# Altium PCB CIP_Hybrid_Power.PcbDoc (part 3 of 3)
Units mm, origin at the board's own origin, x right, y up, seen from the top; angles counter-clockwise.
Board outline 70 x 70 mm, 4 copper layers (Top Layer, GND Pour Layer, Signal Layer 1, Bottom Layer), stack 1.68 mm thick; 202 components, 120 nets, 578 pads, 363 vias.
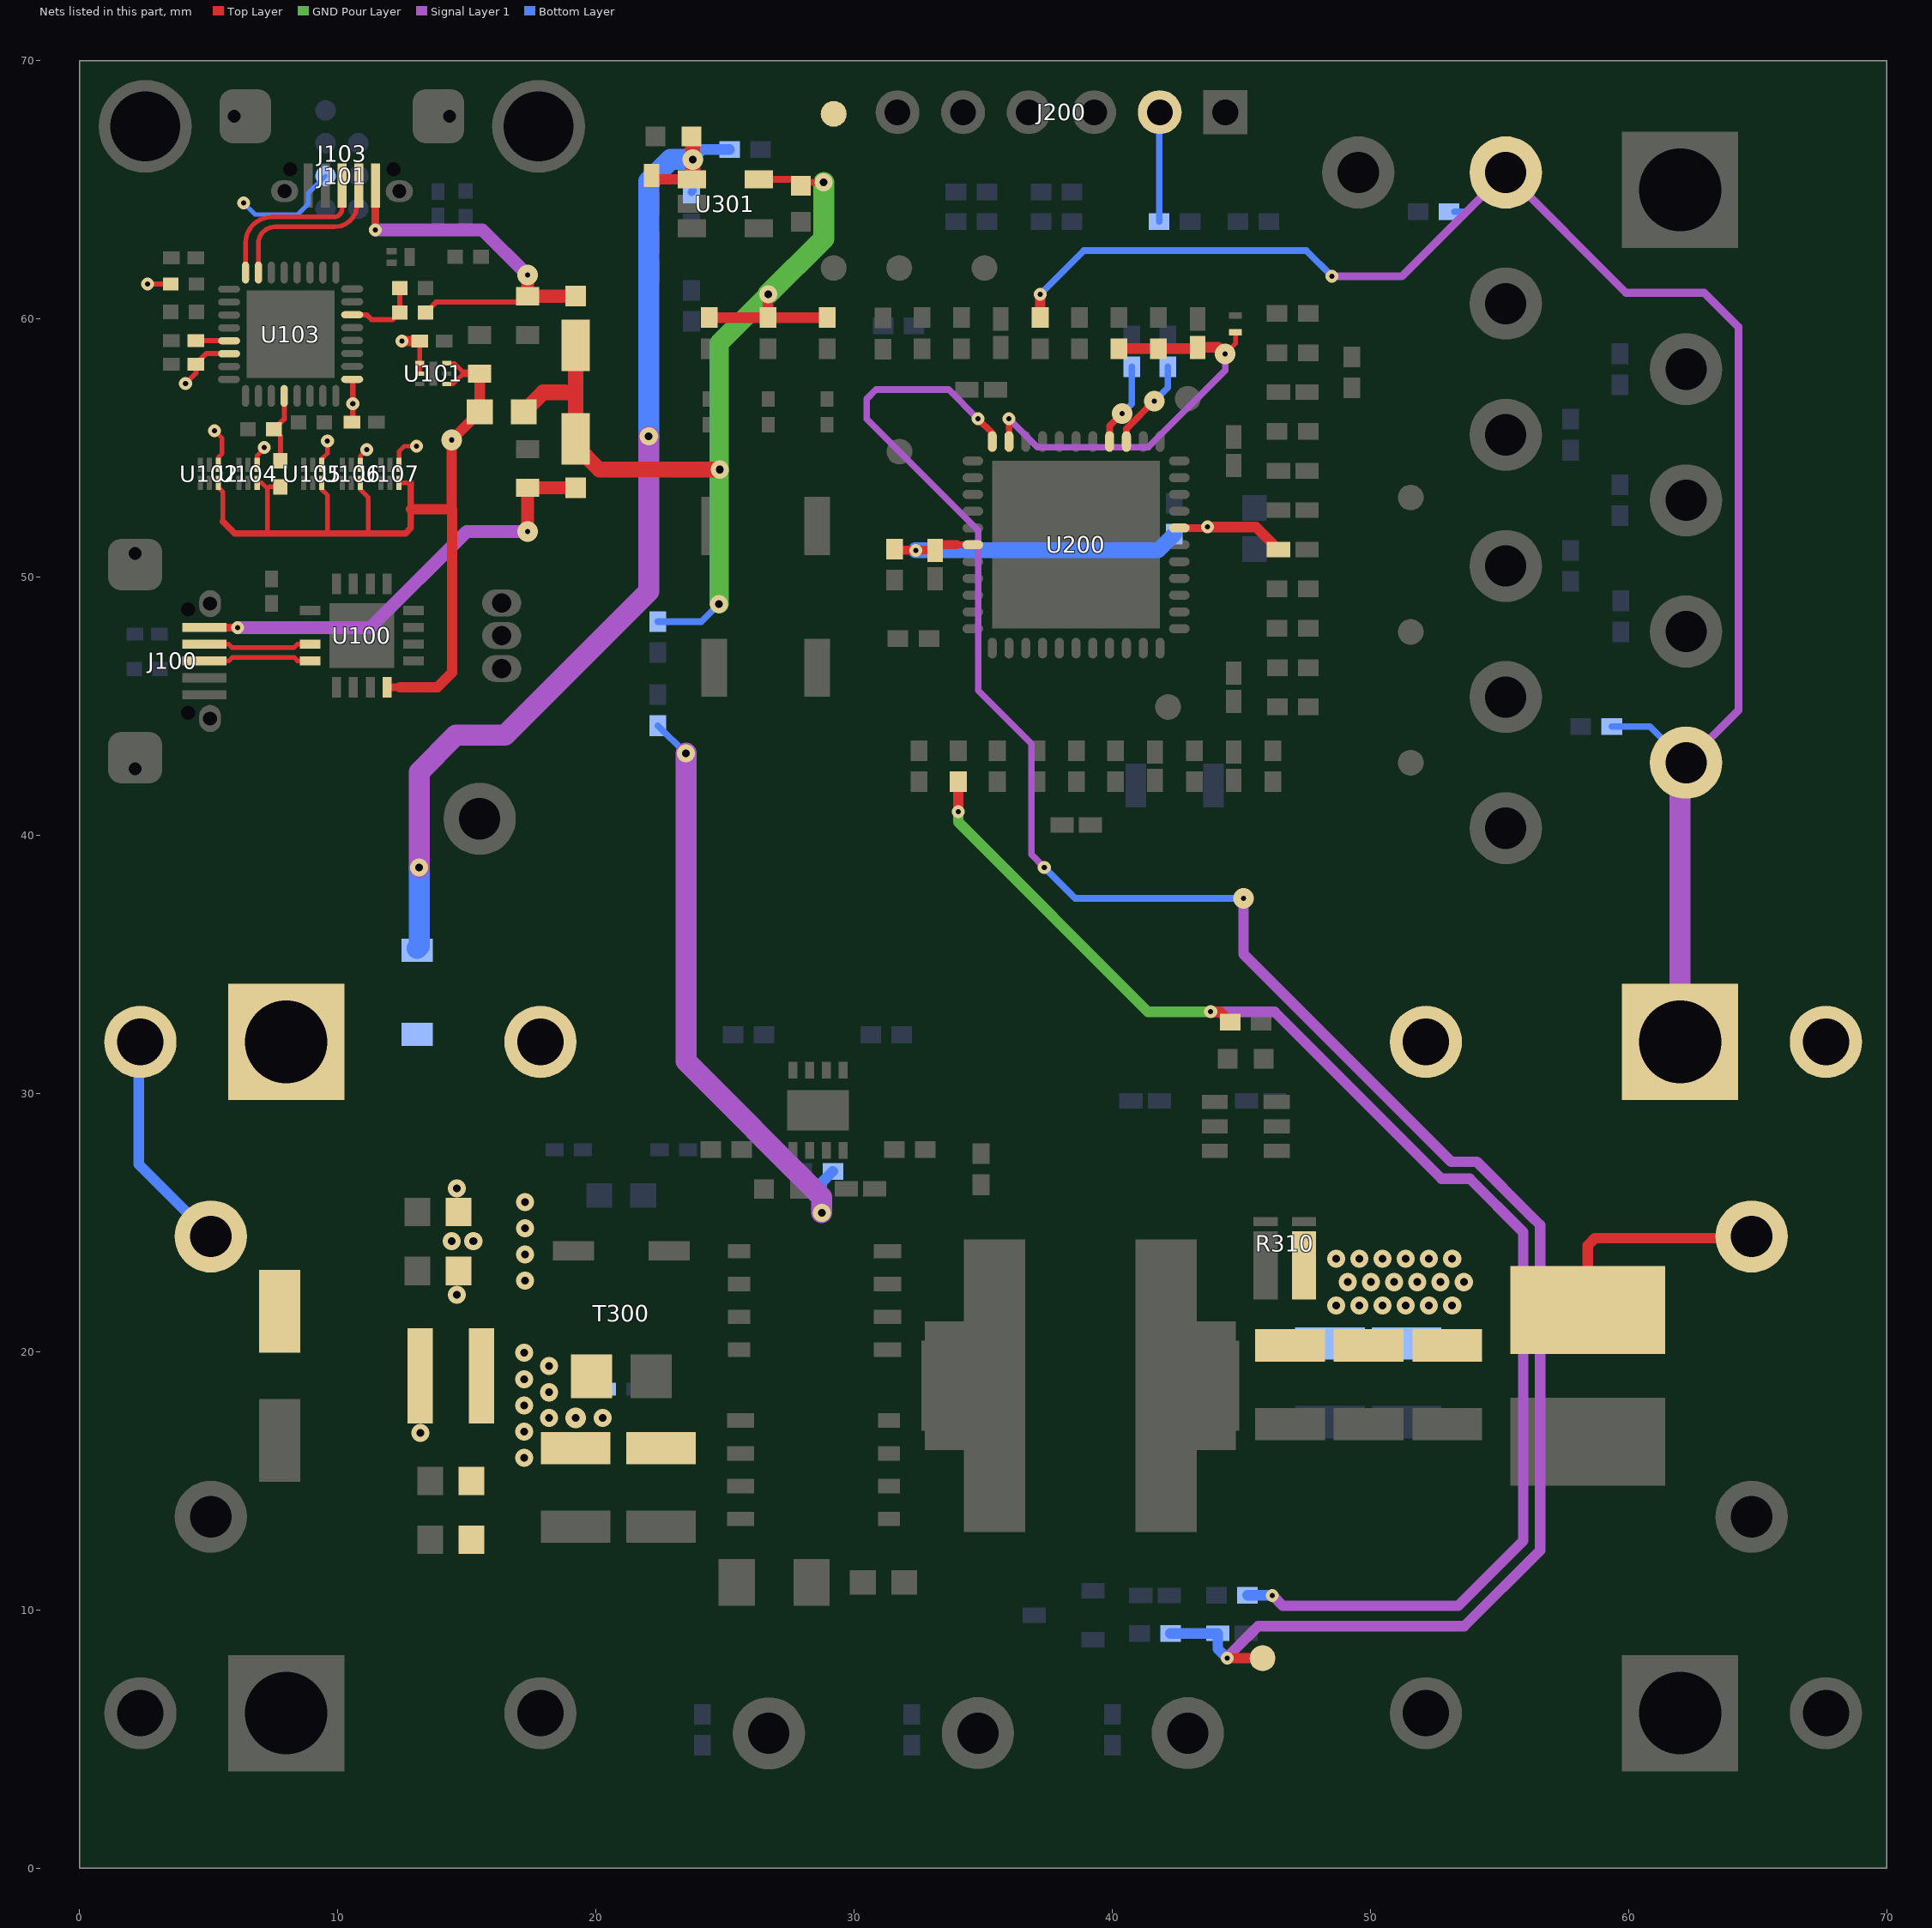
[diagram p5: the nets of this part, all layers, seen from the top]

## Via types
v1: diameter 0.7, hole 0.3, Top Layer to Bottom Layer, 181 vias
v2: diameter 0.5, hole 0.2, Top Layer to Bottom Layer, 103 vias
v3: diameter 0.5/0.5/0.5/0.8 (per signal layer), hole 0.2, Top Layer to Bottom Layer, tented top, 55 vias
v4: diameter 0.7, hole 0.3, Top Layer to Bottom Layer, tented top, 13 vias
v5: diameter 0.7/0.7/0.7/0.8 (per signal layer), hole 0.3, Top Layer to Bottom Layer, tented top, 10 vias
v6: diameter 0.5, hole 0.2, Top Layer to Bottom Layer, tented top, 1 vias

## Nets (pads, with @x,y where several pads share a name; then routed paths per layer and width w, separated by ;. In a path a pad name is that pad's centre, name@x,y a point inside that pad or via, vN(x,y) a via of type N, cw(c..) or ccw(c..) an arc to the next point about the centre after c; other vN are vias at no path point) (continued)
TEMP: C300.2 R300.2 TP203.1 U200.22 | length 84
  Top Layer w0.254: v2(34.798,56.134) 35.35,55.582 U200.22@35.35,55.253
  Top Layer w0.406: v2(44.45,8.128) TP203.1@45.824,8.128
  Signal Layer 1 w0.254: v2(34.798,56.134) 33.663,57.269 30.855,57.269 30.488,56.902 30.488,56.124 34.804,51.807 34.804,45.615 36.865,43.555 36.865,39.259 v2(37.368,38.756)
  Signal Layer 1 w0.406: v2(44.45,8.128) 44.45,8.166 45.65,9.366 53.638,9.366 56.574,12.302 56.574,24.905 56.19,25.29 54.123,27.356 53.127,27.356 45.083,35.401 v3(45.083,37.559)
  Bottom Layer w0.254: v2(37.368,38.756) 38.565,37.559 v3(45.083,37.559)
  Bottom Layer w0.406: R300.2@42.256,9.087 C300.2@44.092,9.087 44.092,8.486 v2(44.45,8.128)
UART_RX: R215.2 U200.14 | length 3.6
  Top Layer w0.254: U200.14@40.55,55.253 40.55,55.743 v3@41.628,56.821
  Bottom Layer w0.254: v3@41.628,56.821 42.156,57.349 R215.2@42.156,58.146
  other v3: 41.625,56.825
UART_TX: R214.2 U200.15 | length 3.2
  Top Layer w0.254: U200.15@39.9,55.253 39.9,55.855 v3(40.378,56.333)
  Bottom Layer w0.254: v3(40.378,56.333) 40.759,56.714 R214.2@40.759,58.146
USB2D_N: J100.2 U100.11 | length 4.2
  Top Layer w0.18: J100.2@4.83,47.4 5.77,47.4 5.896,47.274 8.305,47.274 8.44,47.409 U100.11@8.93,47.409
USB2D_P: J100.3 U100.12 | length 4.2
  Top Layer w0.18: J100.3@4.83,46.75 5.77,46.75 5.914,46.894 8.305,46.894 8.44,46.759 U100.12@8.93,46.759
USBD_N: J103.2 U103.23 | length 6.6
  Top Layer w0.18: U103.23@6.924,61.791 6.924,62.927 cw(c7.567,62.927) 7.567,63.57 9.875,63.57 ccw(c9.875,64.44) 10.745,64.44 J103.2@10.745,65.253
USBD_P: J103.3 U103.24 | length 6.8
  Top Layer w0.18: U103.24@6.424,61.791 6.424,62.935 cw(c7.439,62.935) 7.439,63.95 9.85,63.95 ccw(c9.85,64.26) 10.16,64.26 J103.3@10.16,65.17 J103.3@10.16,65.47
VAUX: C301.2 C302.2 D300.1 R209.2 R318.2 U301.1 | length 42.7
  Top Layer w0.406: C301.2@22.152,65.411 U301.1@23.711,65.411
  Top Layer w0.61: C302.2@23.698,67.075 23.749,67.024 v5(23.749,66.181) U301.1@23.749,65.515
  Signal Layer 1 w0.813: v1(13.15,38.75) 13.15,42.452 14.573,43.875 16.475,43.875 22.046,49.446 v1(22.046,55.449)
  Bottom Layer w0.3: R318.2@23.7,64.91 23.749,64.959 v5@23.749,66.176 ; v5@23.7,66.127 v5@23.749,66.176 ; v5(23.749,66.181) v5@23.749,66.176
  Bottom Layer w0.406: v5@23.749,66.176 24.137,66.564 R209.2@25.181,66.564
  Bottom Layer w0.813: D300.1@13.073,35.625 13.15,35.702 v1(13.15,38.75) ; v1(22.046,55.449) 22.046,65.328 22.899,66.181 v5(23.749,66.181)
VBUS1: C108.1 D200.2 J103.1 R101.2 | length 15.2
  Top Layer w0.2: R101.2@13.4,60.251 13.799,60.65 17.119,60.65 C108.1@17.35,60.881
  Top Layer w0.3: v2@11.46,63.46 J103.1@11.46,65.17
  Top Layer w0.35: v2(11.45,63.45) v2@11.46,63.46 ; D200.2@19.216,60.881 D200.2@19.218,60.883
  Top Layer w0.5: v3(17.35,61.7) C108.1@17.35,60.881 D200.2@19.216,60.881
  Signal Layer 1 w0.5: v2(11.45,63.45) 15.6,63.45 v3(17.35,61.7)
VBUS2: C100.2 D201.2 J100.1 | length 17.6
  Top Layer w0.3: J100.1@4.83,48.05 v2(6.125,48.05)
  Top Layer w0.5: v3(17.35,51.767) C100.2@17.35,53.458 D201.2@19.218,53.458
  Signal Layer 1 w0.5: v2(6.125,48.05) 11.275,48.05 14.992,51.767 v3(17.35,51.767)
VBUS_ADC: R101.1 R103.1 U103.14 | length 3
  Top Layer w0.2: U103.14@10.556,60.164 11.118,60.164 11.307,59.975 12.124,59.975 R101.1@12.4,60.251 ; R101.1@12.4,60.264 R103.1@12.4,61.201
VCC_MCU_CORE: C106.2 U103.29 | length 1.3
  Top Layer w0.2: C106.2@4.5,59.164 4.508,59.156 U103.29@5.787,59.156
VCC_P3V3: C104.2 C107.1 C110.1 D100.2 J101.4 U101.1 U101.2 U102.1 U103.9 U103.30 U104.1 U105.1 U106.1 U107.1 | length 16.4
  Top Layer w0.175: v2(5.225,55.675) 5.513,55.387 5.513,54.775 5.375,54.638 U102.1@5.375,54.351 ; U104.1@6.875,54.351 6.875,54.711 7.15,54.986 v2(7.15,55.025) ; U105.1@9.375,54.351 9.375,54.575 9.6,54.8 v2(9.6,55.276) ; U106.1@10.875,54.351 10.875,54.691 v2(11.125,54.941) ; v2@12.355,59.15 v2@12.357,59.152 ; U107.1@12.375,54.351 12.375,54.875 12.574,55.074 v2(13.053,55.074) ; U101.2@13.175,57.883 U101.1@13.175,58.283 C104.2@13.175,59.152
  Top Layer w0.2: v2(2.631,61.349) D100.2@3.525,61.349 ; v2(4.1,57.5) 4.5,57.9 C107.1@4.5,58.252 4.904,58.656 U103.30@5.787,58.656 ; C110.1@10.495,56.025 10.581,56.111 v2(10.581,56.725) U103.9@10.581,57.664
  Top Layer w0.4: v2(12.48,59.15) 13.173,59.15 C104.2@13.175,59.152
  Bottom Layer w0.175: v2(6.345,64.5) 6.796,64.05 8.45,64.05 8.85,64.45 8.85,64.865 J101.4@9.525,65.54
VCC_P5V0: C202.1 C203.1 C310.1 D200.1 D201.1 J102.2 J200.2 R200.2 R201.2 R205.1 R206.2 R207.2 R208.2 R220.1 R221.1 R235.2 R302.2 R305.2 R312.2 TP200.1 U200.7 U200.28 U301.5 | length 141
  Top Layer w0.254: U301.5@26.311,65.411 27.681,65.411 C310.1@27.932,65.16 28.066,65.294 v1(28.821,65.294) ; 33.975,51.253 U200.28@34.6,51.253
  Top Layer w0.3: U200.7@42.6,51.903 v2@43.648,51.903
  Top Layer w0.35: R201.2@31.566,51.091 31.616,51.041 v2(32.385,51.041) C203.1@33.139,51.041 33.351,51.253 33.975,51.253
  Top Layer w0.356: v2@43.648,51.903 v2(43.688,51.943)
  Top Layer w0.406: R206.2@24.384,60.052 R207.2@26.67,60.052 ; v1(26.67,60.96) R207.2@26.67,60.052 ; R208.2@28.956,60.052 R207.2@26.67,60.052 ; v2(34.036,40.91) R235.2@34.036,42.072 ; v2(43.688,51.943) 45.567,51.943 C202.1@46.44,51.07 ; v2(43.815,33.166) 44.174,33.166 R312.2@44.574,32.766
  Top Layer w0.6: 18.775,57.154 19.176,57.154 19.218,57.195 ; D200.1@19.218,58.983 19.218,57.195 ; v1(24.8,54.168) 20.134,54.168 19.218,55.085 D201.1@19.218,55.358 19.218,57.195
  Top Layer w0.61: J102.2@17.2,56.404 17.95,57.154 18.775,57.154
  Signal Layer 1 w0.406: v2(43.815,33.166) 46.289,33.166 52.755,26.7 53.851,26.7 55.918,24.633 55.918,12.676 53.402,10.16 46.609,10.16 v2@46.201,10.568
  Signal Layer 1 w0.813: v1(23.487,43.18) 23.487,31.25 28.75,25.987 v1(28.75,25.384)
  GND Pour Layer w0.406: v2(34.036,40.91) 34.036,40.513 41.383,33.166 v2(43.815,33.166)
  GND Pour Layer w0.75: v1(24.765,48.96) 24.765,59.055 v1(26.67,60.96)
  GND Pour Layer w0.813: v1(26.67,60.96) 28.822,63.112 v1(28.821,65.294)
  Bottom Layer w0.254: R220.1@22.401,44.247 23.469,43.18 v1(23.487,43.18) ; R221.1@22.401,48.275 24.08,48.275 v1(24.765,48.96) ; R205.1@41.818,63.77 41.818,67.985 J200.2@41.841,68.008
  Bottom Layer w0.406: v1(28.75,25.384) 28.75,26.561 R305.2@29.177,26.988 ; R302.2@45.242,10.561 v2(46.194,10.561)
  Bottom Layer w0.61: v2(32.385,51.041) 41.782,51.041 R200.2@42.41,51.669
VCC_P5V0_P20V0: C306.2 C307.2 C308.2 C309.1 D303.1 L300.2 T300.3
  other v1: 17.219,15.888 17.219,16.904 18.19,17.431 20.256,17.431 17.219,17.92 18.19,18.425 17.219,18.936 18.19,19.45 17.219,19.968
  other v5: 19.215,17.431
VCC_P5V0_STRAP: C103.2 J102.1 R102.2 U100.16 U101.4 U101.6 U102.6 U104.6 U105.6 U106.6 U107.6 | length 36.6
  Top Layer w0.175: U102.6@5.375,53.651 5.375,53.475 5.55,53.3 5.55,52.155 ; U104.6@6.875,53.651 7.049,53.651 7.275,53.425 ; 7.275,51.774 7.275,53.425 ; R102.2@7.775,53.502 7.352,53.502 7.275,53.425 ; U105.6@9.375,53.651 9.375,53.4 9.6,53.175 9.6,51.774 ; U106.6@10.875,53.651 10.875,53.4 11.176,53.099 11.176,51.774 ; U107.6@12.4,53.651 12.827,53.651 ; U101.4@14.225,57.483 14.471,57.483 14.893,57.906 14.516,58.283 U101.6@14.225,58.283
  Top Layer w0.25: 5.55,52.155 6.007,51.698 12.622,51.698 12.827,51.903 12.827,52.627 12.827,53.651 ; C103.2@15.439,57.906 C103.2@15.494,57.851
  Top Layer w0.3: U100.16@11.905,45.734 12.4,45.734 ; 14.893,57.906 C103.2@15.439,57.906
  Top Layer w0.4: 12.4,45.734 13.859,45.734 14.425,46.3 14.425,52.641 14.411,52.627 ; 12.827,52.627 14.411,52.627 ; C103.2@15.494,57.851 15.5,57.845 J102.1@15.5,56.404 v3(14.411,55.315) 14.411,52.627
VIN: C303.1 C304.2 C305.2 D300.2 J300.1 J300.2 L300.1 pad.1@8,32 TP300.1 | length 8.5
  Bottom Layer w0.406: J300.1@2.286,31.83 2.286,27.258 TP300.1@5.08,24.464
  other v1: 13.192,16.854 14.605,22.199 17.252,22.749 17.252,23.765 14.411,24.275 15.25,24.275 17.252,24.781 17.252,25.797 14.605,26.322
VIN_FF: C204.1 D202.2 R212.2 R213.2 U200.21 | length 16.8
  Top Layer w0.175: v3(44.377,58.652) 44.776,59.051 D202.2@44.776,59.484
  Top Layer w0.254: U200.21@36,55.253 v2(36,56.134)
  Top Layer w0.406: R212.2@40.259,58.852 R213.2@41.783,58.852 43.257,58.852 C204.1@43.307,58.902 44.127,58.902 v3(44.377,58.652)
  Signal Layer 1 w0.254: v2(36,56.134) 37.1,55.034 41.395,55.034 44.377,58.015 v3(44.377,58.652)
VOUT: C314.2 C315.2 C316.2 C317.2 C318.2 C319.1 J302.1 J302.2 pad.1@62,32 pad.2@58.42,21.616 R229.2 R230.2 R301.2 R310.1 TP211.1 TP212.1 TP213.1 | length 76.2
  Top Layer w0.406: R301.2@37.211,60.052 v2(37.211,60.96) ; C319.1@58.42,22.241 58.42,24.12 58.7,24.4 TP211.1@64.77,24.4
  Signal Layer 1 w0.305: v2(48.514,61.654) 51.224,61.654 TP213.1@55.245,65.675 59.903,61.017 62.935,61.017 64.262,59.69 64.262,44.847 TP212.1@62.23,42.815
  Signal Layer 1 w0.813: pad.1@62,32 TP212.1@62,42.815
  Bottom Layer w0.254: v2(37.211,60.96) 38.901,62.65 47.518,62.65 v2(48.514,61.654) ; R229.2@53.251,64.151 53.721,64.151 TP213.1@55.245,65.675 ; R230.2@59.352,44.212 60.833,44.212 TP212.1@62.23,42.815
  other v1: 48.67,21.795 49.57,21.795 50.47,21.795 51.37,21.795 52.27,21.795 53.17,21.795 49.12,22.695 50.02,22.695 50.92,22.695 51.82,22.695 52.72,22.695 53.62,22.695 48.67,23.595 49.57,23.595 50.47,23.595 51.37,23.595 52.27,23.595 53.17,23.595
VTG_ADC: R102.1 R104.2 U103.4 | length 2.8
  Top Layer w0.2: R102.1@7.775,54.502 7.775,55.474 R104.2@7.524,55.725 7.924,56.125 U103.4@7.924,57.02
pads on no net: J100.0 J100.4 J100.10 J100.11 J101.3 J103.0 J103.4 J103.10 J103.11 J200.6 TP211.0 TP212.0 TP213.0 TP214.0 TP215.0 TP216.0 TP217.0 TP218.0 TP219.0 TP220.0 TP221.0 TP222.0 TP223.0 TP224.0 TP225.0 TP300.0 TP301.0 TP302.0 TP303.0 U100.1 U100.2 U100.3 U100.4 U100.5 U100.6 U100.7 U100.14 U100.15 U100.17 U101.5 U103.3 U103.6 U103.13 U103.18 U103.22 U200.13 U200.29 U200.31 U200.45 U301.4 U302.9
copper on no net: | length 11.4
  Bottom Layer w0.15: 38.126,19.063 38.761,18.428 ; 38.126,18.301 39.142,19.317 ; 38.38,18.047 38.761,18.428 ; 38.38,19.317 39.396,18.301 ; 38.735,18.402 38.761,18.428 ; 38.76,17.92 38.76,19.439 ; 39.472,18.428 38.761,18.428 ; 39.523,18.682 ccw(c38.761,18.682) 39.523,18.682

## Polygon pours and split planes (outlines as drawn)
VCC_P5V0_STRAP on Top Layer "Levelshifters" (solid, pour order 152): 5.025,53.925 13.159,53.925 13.159,51.884 12.85,51.575 5.483,51.575 5.025,52.033
GND on Top Layer "relief" (solid, remove dead copper, pour order 301): 20.955,34.163 21.22,33.925 33.084,33.925 39.7,27.309 44.284,27.309 45.572,26.017 47.625,26.017 49.276,27.668 49.276,32.766 51.562,35.052 64.33,35.052 65.151,34.231 65.151,17.78 70,17.78 70,70 29.499,70 29.499,65.858 25.325,65.858 25.325,70 0,70 0,37.55 0.75,36.8 20.655,36.8 20.955,36.5
GND on Top Layer "full" (solid, remove dead copper, pour order 222): 20.955,32.616 21.351,33.016 32.747,33.016 37.592,28.171 37.592,27.25 33.02,27.25 33.02,26.733 31.703,25.416 21.602,25.416 20.075,23.679 20.075,23.51 19.836,23.25 18.475,23.25 18.214,23.5 18.214,26.666 19.028,27.5 20.248,27.5 20.955,28.207
DCR_L on Top Layer "full" (solid, remove dead copper, pour order 204): 40.64,26.926 44.372,26.926 45.174,26.124 45.174,24.927 45.463,24.638 46.59,24.638 46.59,21.749 46.187,21.349 44.958,21.349 44.958,12.442 44.698,12.182 40.904,12.182 40.64,12.446
VOUT on Top Layer "full" (solid, remove dead copper, pour order 180): 50.184,32.474 52,34.29 64.33,34.29 64.33,29.542 64.33,20.187 63.709,19.566 55.372,19.566 54.838,20.066 54.354,20.066 54.354,19.566 45.331,19.566 45.209,19.685 45.209,20.949 45.337,21.082 46.431,21.082 46.804,21.455 46.804,24.638 48.087,24.638 50.184,26.643
GND on Top Layer "full" (solid, remove dead copper, pour order 176): 0.762,18.796 8.652,18.796 9.144,19.288 9.144,26.417 10.153,27.426 12.714,27.426 13.574,26.566 13.574,22.583 12.812,21.844 11.938,21.844 11.684,21.59 11.684,16.256 11.938,16.002 13.462,16.002 14.125,15.339 14.15,11.6 14.765,11 16.95,11 17.518,11.568 17.518,13.962 18.415,14.859 23.702,14.859 24.384,15.502 24.384,17.653 25.273,18.542 25.908,18.542 26.16,18.288 26.16,14.347 26.071,14.068 24.851,14.045 24.711,13.85 24.732,12.508 25.093,12.147 25.86,12.135 26.16,11.953 26.16,8.382 27.257,7.399 36.693,7.399 37.601,8.269 37.589,11 38.046,11.43 44.749,11.43 45.407,12.135 45.407,17.801 45.64,18.034 54.229,18.034 54.356,17.907 54.61,17.907 54.61,10.16 54.902,10.16 54.902,17.907 54.999,18.186 55.245,18.415 68.834,18.415 69.342,17.907 69.342,1.394 68.834,0.902 48.893,0.902 48.406,0.27 22.844,0.27 22.85,3.275 22.475,3.615 22.098,3.275 22.098,1.016 21.844,0.762 0.762,0.762 0.508,1.016 0.508,13.605 0.508,18.542
VCC_P5V0_P20V0 on Top Layer "full" (solid, remove dead copper, pour order 168): 15.238,21.084 19.565,21.075 20.574,20.066 20.828,19.812 20.828,18.031 21.206,17.653 23.876,17.653 24.003,17.526 24.028,15.815 23.64,15.426 18.106,15.426 17.044,14.364 17.029,11.76 16.75,11.481 15.181,11.481 14.916,11.746 14.916,20.763
VIN on Top Layer "full" (solid, remove dead copper, pour order 166): 13.97,22.347 12.832,21.209 12.573,21.209 12.446,21.081 12.446,16.614 12.573,16.488 13.741,16.488 13.869,16.637 13.869,20.6 14.605,21.336 17.145,21.336 17.78,21.971 17.78,26.998 18.722,27.94 20.066,27.94 20.32,28.2 20.32,35.814 20.066,36.068 0.762,36.068 0.508,35.814 0.508,19.544 0.762,19.304 8.39,19.304 8.63,19.544 8.63,26.669 9.901,27.94 12.948,27.94 13.97,26.918
SW_NODE on Top Layer "full" (solid, remove dead copper, pour order 164): 30.988,23.114 30.734,22.86 30.729,19.014 30.258,18.542 26.924,18.542 26.67,18.288 26.67,8.784 27.329,8.13 36.197,8.13 36.829,8.762 36.761,26.63 36.418,26.94 33.658,26.94 33.02,26.302 33.02,23.994 32.188,23.114
NetD303_2 on Top Layer "full" (solid, remove dead copper, pour order 162): 21.362,20.103 21.087,19.828 21.087,18.195 21.362,17.92 24.127,17.92 25.143,18.936 29.998,18.936 30.252,19.19 30.252,24.778 29.998,25.032 24.918,25.032 24.13,24.244 24.128,22.638
NetQ301_4 on Top Layer "full" (solid, pour order 160): 26.063,12.557 25.841,12.335 25.171,12.335 24.92,12.586 24.92,13.856 26.063,13.856
VCC_P5V0 on Top Layer "VCC_P5V0" (solid, remove dead copper, pour order 158): 25.317,64.947 30.15,64.947 30.15,69.025 40.675,69.025 40.675,67.025 42.997,67.025 42.997,70 25.319,70
NetD303_2 on Bottom Layer "full" (solid, pour order 321): 21.5,19.25 21.175,18.925 21.175,18.075 21.5,17.75 23.5,17.75 23.75,18 23.75,19.75 23.5,20 22.75,20 22,19.25
VCC_P5V0_P20V0 on Bottom Layer "full" (solid, remove dead copper, pour order 319): 16.674,20.574 17.798,20.572 18.224,20.138 18.277,19.478 18.505,19.25 20.5,19.25 21,18.75 21,16.25 19.99,15.24 16.49,15.24 16.256,15.51 16.256,20.156
GND on Bottom Layer "relief" (solid, remove dead copper, pour order 298): 20.914,34.231 21.22,33.925 33.084,33.925 39.433,27.576 46.391,27.576 49.276,30.416 49.276,32.766 51.562,35.052 64.33,35.052 65.151,34.231 65.151,17.78 70,17.78 70,70 0.5,70 0.5,37.251 0.763,37 20.099,36.975 20.918,36.107
GND on Bottom Layer "full" (solid, remove dead copper, pour order 309): 0.762,18.796 8.652,18.796 9.144,19.288 9.144,26.417 10.153,27.426 12.714,27.426 13.574,26.566 13.574,22.583 12.812,21.844 11.938,21.844 11.684,21.59 11.684,16.256 11.938,16.002 13.473,16.002 14.616,14.859 18.415,14.859 23.267,14.859 24.72,13.25 24.732,12.508 25.093,12.147 25.86,12.135 26.16,11.953 26.16,8.382 27.257,7.399 36.693,7.399 37.601,8.269 37.589,11 39.192,12.508 44.707,12.508 45.407,13.258 45.407,17.801 45.64,18.034 54.229,18.034 54.356,17.907 54.61,17.907 54.61,10.16 54.902,10.16 54.902,17.907 54.999,18.186 55.245,18.415 68.834,18.415 69.342,17.907 69.342,1.394 68.834,0.902 48.893,0.902 48.406,0.27 22.844,0.27 22.85,3.275 22.475,3.615 22.098,3.275 22.098,1.016 21.844,0.762 0.762,0.762 0.508,1.016 0.508,13.605 0.508,18.542
GND on Bottom Layer "full" (solid, remove dead copper, pour order 311): 20.955,32.616 21.351,33.016 32.747,33.016 38.225,27.538 38.225,27.25 33.525,27.25 31.016,24.741 26.575,24.75 24.116,24.75 23.259,23.775 18.908,23.775 18.25,24.375 18.25,26.722 19.028,27.5 20.248,27.5 20.955,28.207
VOUT on Bottom Layer "full" (solid, remove dead copper, pour order 274): 50.184,32.474 52,34.29 64.33,34.29 64.33,29.542 64.33,20.187 63.709,19.566 55.372,19.566 54.838,20.066 54.354,20.066 54.354,19.566 45.331,19.566 45.209,19.685 45.209,20.949 45.337,21.082 46.606,21.082 46.99,21.466 46.99,26.865 50.184,30.059
VIN on Bottom Layer "full" (solid, remove dead copper, pour order 266): 13.97,22.347 12.832,21.209 12.573,21.209 12.446,21.081 12.446,16.614 12.573,16.488 13.741,16.488 13.869,16.637 13.869,20.6 14.605,21.336 17.145,21.336 17.78,21.971 17.78,26.998 18.722,27.94 20.066,27.94 20.32,28.2 20.32,35.814 20.066,36.068 0.762,36.068 0.508,35.814 0.508,19.544 0.762,19.304 8.39,19.304 8.63,19.544 8.63,26.669 9.901,27.94 12.948,27.94 13.97,26.918
DCR_L on Bottom Layer "full" (solid, remove dead copper, pour order 242): 40,26.682 40.369,27.051 46.101,27.051 46.482,26.682 46.482,21.844 46.233,21.59 43.942,21.59 43.688,21.844 43.688,24.89 40.256,24.89 40,25.146
SW_NODE on Bottom Layer "full" (solid, remove dead copper, pour order 220): 30.48,23.296 30.48,18.796 29.972,18.288 27.178,18.288 26.67,17.78 26.67,8.89 27.178,8.382 40,8.382 40,12.545 38.213,12.544 38.195,26.33 37.855,26.67 33.854,26.67
GND on GND Pour Layer "full" (solid, remove dead copper, pour order 296): 22.85,0.27 48.406,0.27 48.893,0.902 68.839,0.902 69.215,1.27 69.215,28.518 68.833,28.9 56.084,28.9 55.059,27.875 55.059,18.034 54.932,17.907 54.356,17.907 54.229,18.034 45.64,18.034 45.337,17.731 45.337,12.222 44.818,11.703 38.319,11.703 37.589,10.973 37.601,8.269 36.693,7.367 26.15,7.367 24.25,9.268 24.25,11.525 23.272,12.503 23.272,23.78 23.758,24.266 24.761,24.261 25.753,25.278 31.018,25.248 33.02,27.25 38.653,27.25 38.678,27.628 33.02,33.274 21.206,33.274 20.955,33.02 20.955,28.067 20.322,27.434 12.529,27.434 12.25,27.148 12.25,23.254 12.25,16.275 11.962,15.987 11.675,16.275 11.675,27.225 11.474,27.426 10.153,27.426 9.144,26.417 9.144,19.288 8.652,18.796 0.762,18.796 0.508,18.542 0.508,13.605 0.508,1.016 0.762,0.762 21.844,0.762 22.098,1.016 22.098,3.25 22.475,3.65 22.85,3.25
VOUT on GND Pour Layer "full" (solid, remove dead copper, pour order 278): 51.435,34.29 68.58,34.29 69.596,33.274 69.596,30.734 68.58,29.718 55.245,29.718 54.102,28.575 54.102,21.69 53.353,20.942 48.722,20.942 48.084,21.58 48.084,30.939
GND on GND Pour Layer "full" (solid, remove dead copper, pour order 260): 29.499,70 24.9,70 0.508,70 0.508,37.025 0.75,36.75 20.5,36.75 20.955,36.295 20.955,34.163 21.22,33.925 32.996,33.925 39.671,27.25 45.905,27.25 46.99,28.318 46.99,30.94 51.275,35.225 70,35.225 70,70
VCC_P5V0_P20V0 on GND Pour Layer "full" (solid, remove dead copper, pour order 206): 16.674,20.574 17.798,20.572 18.675,19.679 18.675,19.395 18.82,19.25 20.5,19.25 21,18.75 21,16.25 19.99,15.24 16.49,15.24 16.256,15.51 16.256,20.156
VIN on GND Pour Layer "full" (solid, remove dead copper, pour order 258): 9.901,27.94 18.041,27.94 20.066,27.94 20.32,28.2 20.32,35.814 20.066,36.068 0.762,36.068 0.508,35.814 0.508,19.544 0.762,19.304 8.39,19.304 8.63,19.544 8.63,26.669
SW_NODE on GND Pour Layer "full" (solid, remove dead copper, pour order 252): 30.511,23.496 30.511,19.05 29.845,18.415 27.305,18.415 26.693,17.78 26.669,8.637 27.176,8.13 36.07,8.13 36.83,8.89 36.83,26.035 36.195,26.67 33.656,26.67
no net on Bottom Solder "0.3mm" (solid, pour order 152): 22.86,3.048 47.117,3.048 47.117,0.27 22.86,0.27
no net on Bottom Solder "0.3mm" (solid): 64.754,39.004 64.775,53.704 64.775,70 70,70 70,39.004
no net on Top Solder "0.3mm" (solid): 22.86,3.032 47.117,3.032 47.117,0.254 22.86,0.254
no net on Top Solder "0.3mm" (solid): 64.77,39.004 64.77,62.125 57.785,62.125 57.785,70 70,70 70,39.004
GND on Signal Layer 1 "full" (solid, remove dead copper, pour order 317): 22.85,0.27 48.406,0.27 48.893,0.902 68.839,0.902 69.215,1.27 69.215,28.518 68.833,28.9 56.084,28.9 55.059,27.875 55.059,18.034 54.932,17.907 54.356,17.907 54.229,18.034 45.64,18.034 45.337,17.731 45.337,12.222 44.818,11.703 38.319,11.703 37.589,10.973 37.601,8.269 36.693,7.367 26.133,7.367 24.237,9.263 24.237,11.512 23.272,12.477 23.272,23.78 24.237,24.744 26.503,24.753 27.021,25.271 31.496,25.246 33.475,27.225 38.725,27.225 38.725,27.58 33.02,33.274 21.206,33.274 20.955,33.02 20.955,28.067 20.322,27.434 12.529,27.434 12.25,27.148 12.25,23.254 12.25,16.275 11.962,15.987 11.675,16.275 11.675,27.225 11.474,27.426 10.153,27.426 9.144,26.417 9.144,19.288 8.652,18.796 0.762,18.796 0.508,18.542 0.508,13.605 0.508,1.016 0.762,0.762 21.844,0.762 22.098,1.016 22.098,3.25 22.475,3.65 22.85,3.25
VCC_P5V0_P20V0 on Signal Layer 1 "full" (solid, remove dead copper, pour order 228): 16.674,20.574 17.798,20.572 18.675,19.694 18.675,19.395 18.82,19.25 20.5,19.25 21,18.75 21,16.25 19.99,15.24 16.49,15.24 16.256,15.51 16.256,20.156
GND on Signal Layer 1 "Signal Layer 1-GND" (solid, pour order 234): 46.99,70 46.99,64.008 47.498,63.5 48.768,63.498 49.529,62.737 49.529,38.054 46.5,35.025 23.15,35.025 22.475,35.7 22.475,48.927 17.548,44 0.768,44 0.508,43.732 0.508,37.075 0.775,36.8 20.268,36.8 20.988,35.979 21.071,34.279 21.429,33.775 33.306,33.775 41.856,25.225 54,25.225 54,28.9 51.525,28.925 49.75,30.625 49.75,33.5 51.525,35.275 70,35.275 70,70
VIN on Signal Layer 1 "full" (solid, remove dead copper, pour order 315): 12.948,27.94 18.722,27.94 20.066,27.94 20.32,28.2 20.32,35.814 20.066,36.068 0.762,36.068 0.508,35.814 0.508,19.544 0.762,19.304 8.39,19.304 8.63,19.544 8.63,26.669 9.901,27.94
VOUT on Signal Layer 1 "full" (solid, remove dead copper, pour order 305): 50.546,33.274 51.562,34.29 68.563,34.29 69.596,33.257 69.596,30.734 68.58,29.718 51.562,29.718 50.546,30.734
VOUT on Signal Layer 1 "full" (solid, remove dead copper, pour order 286): 48.006,24.648 54.356,24.639 54.356,20.827 48.006,20.828
VCC_P5V0 on Signal Layer 1 "VCC_P5V5" (solid, pour order 280): 23.495,69.485 46.482,69.485 46.482,63.754 47.244,62.992 48.537,62.992 49.022,62.492 49.022,38.322 46.26,35.56 23.815,35.56 22.86,36.515 22.86,68.85
VCC_P3V3 on Signal Layer 1 "VCC_P3V3" (solid, remove dead copper, pour order 276): 0,70 21.35,70 21.35,49.537 16.27,44.525 0,44.525
SW_NODE on Signal Layer 1 "full" (solid, remove dead copper, pour order 238): 30.48,23.495 30.48,19.05 29.845,18.415 27.305,18.415 26.67,17.78 26.67,8.89 27.305,8.255 35.98,8.255 36.693,8.968 36.693,25.732 35.755,26.67 33.655,26.67

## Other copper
Top Layer:
  pour cut-out: 20.5,0 20,0 20,6.8 19.045,7.755 12.72,7.755 11.675,8.8 11.675,12.575 11.95,12.843 12.238,12.575 12.238,9.085 13.047,8.275 19.325,8.275 20.5,7.1
  pour cut-out: 48.552,0 48.26,0 48.26,9.398 48.552,9.398
  pour cut-out: 54.902,10.16 54.61,10.16 54.61,27.94 54.902,27.94
Signal Layer 1:
  pour cut-out: 20.5,0 20,0 20,6.8 19.045,7.755 12.72,7.755 11.675,8.8 11.675,12.575 11.95,12.843 12.238,12.575 12.238,9.085 13.047,8.275 19.325,8.275 20.5,7.1
  pour cut-out: 48.533,0 48.241,0 48.241,9.398 48.533,9.398
  pour cut-out: 54.902,10.16 54.61,10.16 54.61,27.94 54.902,27.94
  pour cut-out: 18.75,23.791 18.75,19.32 23.25,19.32 23.25,23.791
  pour cut-out: 13.198,20.375 13.186,17.857 15.562,17.857 15.562,20.375
  pour cut-out: 44.277,12.532 34.29,12.532 34.29,24.807 44.249,24.807
GND Pour Layer:
  pour cut-out: 20.5,0 20,0 20,6.8 19.045,7.755 12.72,7.755 11.675,8.8 11.675,12.575 11.95,12.843 12.238,12.575 12.238,9.085 13.047,8.275 19.325,8.275 20.5,7.1
  pour cut-out: 13.198,20.375 13.186,17.857 15.562,17.857 15.562,20.375
  pour cut-out: 48.533,0 48.241,0 48.241,9.398 48.533,9.398
  pour cut-out: 54.902,10.16 54.61,10.16 54.61,27.94 54.902,27.94
  pour cut-out: 18.75,23.791 18.75,19.32 23.25,19.32 23.25,23.791
  pour cut-out: 44.364,12.545 34.29,12.544 34.29,24.819 44.336,24.82
Bottom Layer:
  pour cut-out: 13.216,20.375 13.204,17.857 15.58,17.857 15.58,20.375
  pour cut-out: 20.5,0 20,0 20,6.8 19.045,7.755 12.72,7.755 11.675,8.8 11.675,12.575 11.95,12.843 12.238,12.575 12.238,9.085 13.047,8.275 19.325,8.275 20.5,7.1
  pour cut-out: 48.533,0 48.241,0 48.241,9.398 48.533,9.398
  pour cut-out: 54.902,10.16 54.61,10.16 54.61,27.94 54.902,27.94
  pour cut-out: 18.75,23.765 18.75,19.354 22.119,19.354 22.816,20.05 23.25,20.05 23.25,23.765
  pour cut-out: 43.194,12.545 34.316,12.544 34.316,24.819 43.167,24.82

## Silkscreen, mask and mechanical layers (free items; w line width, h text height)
Top Overlay:
  circle w0.4: c46.35,69.175 r0.2
  lines w0.254: 0.4,41.65 5.15,41.65 8.05,44.55 19.875,44.55 21.13,45.805 21.13,69.575 ; 0.4,52.454 21.125,52.454 ; 31.825,41.325 34.7,41.325 34.7,44 31.825,44 31.825,41.325
  text "VDD" at 26.45,67.57 h0.75
  text "VOUT" at 52.47,65.967 h1 r45
  text "C2INJ" at 46.457,65.558 h1 r45
  text "ICSP/ICD" at 34.75,65.15 h1
  text "DEBUGGER" at 3.425,62.75 h1
  text "C3INJ" at 30.063,62.75 h0.75
  text "HSCS_FB" at 23.43,61.664 h0.75
  text "COMP3" at 35.825,61.601 h0.75
  text "PS" at 2.725,60.825 h0.75 r90
  text "COMP2" at 51.358,59.814 h1 r45
  text "DCR_CS" at 58.126,57.225 h1 r45
  text "RB3" at 40.159,56.537 h0.75
  text "RA4" at 30.823,55.65 h0.75
  text "LED1" at 25.85,55.35 h0.75 r90
  text "LED2" at 28.125,55.35 h0.75 r90
  text "LED3" at 30.425,55.35 h0.75 r90
  text "HS_CS" at 51.308,54.78 h1 r45
  text "RB0" at 48.8,52.711 h0.75
  text "CT_CS" at 58.35,52.325 h1 r45
  text "I2C BRIDGE" at 6.275,50.75 h1
  text "PWM_HS" at 50.658,49.1 h1 r45
  text "SDA" at 17.95,48.479 h0.75
  text "RD7" at 48.8,47.504 h0.75
  text "SCL" at 17.95,47.209 h0.75
  text "PWM_LS" at 57.658,46.625 h1 r45
  text "GND" at 17.95,45.939 h0.75
  text "PIC16F1779" at 35.039,45.65 h0.75
  text "SW1" at 25.75,45.35 h0.75
  text "C1INJ" at 51.7,44.9 h1 r45
  text "RC5" at 39.391,44.599 h0.75
  text "VOUT" at 58.801,42.672 h1 r45
  text "RD6" at 48.8,42.44 h0.75
  text "DEBUG" at 11.925,40.25 h1 r45
  text "COMP1" at 51.558,39.739 h1 r45
  text "R" at 5.168,37.7 h3
  text "*h" at 23.311,35.652 h5.5
  text "CIP Hybrid Power / Starter Kit" at 30.3,33.39 h1
  text "+6...16V DC" at 0.475,24.631 h1 r270
  text "+" at 58.087,24.234 h1
  text "VIN" at 8.25,24.125 h1 r45
  text "VOUT" at 60.515,23.384 h1 r45
  text "+INPUT-" at 2.314,23.155 h1.3 r270
  text "-OUTPUT+" at 67.885,13.566 h1.4 r90
  text "GND" at 60.515,11.938 h1 r44.86
  text "+0.5...5.0V DC" at 69.6,11.656 h1 r90
  text "GND" at 7.62,11.462 h1 r45
  text "TEMP" at 44.45,8.925 h0.75
  text "GATE_L" at 22.975,4.825 h1 r45
  text "SW_NODE" at 39.02,4.53 h1 r45
  text "GATE_H" at 30.75,4.45 h1 r45
Bottom Overlay:
  text "NC" at 32.306,65.975 h0.6
  text "CLK" at 35.146,65.975 h0.6
  text "DATA" at 37.986,65.975 h0.6
  text "GND" at 40.226,65.975 h0.6
  text "P5V0" at 43.066,65.975 h0.6
  text "MCLR" at 45.606,65.975 h0.6
  text "c" at 62.476,21.015 h7
  text "r" at 67.925,16.275 h7
  text "t" at 61.975,13.475 h9
  text "A08-2919 Rev 2" at 7.55,12.923 h2 r270
  text "Microchip © 2018" at 13.525,11.6 h2 r270
Top Solder:
  region: 46.9,24.925 46.9,24.575 47.958,24.575 47.958,24.925
  region: 46.475,24.575 46.475,24.925 45.417,24.925 45.417,24.575
Board (M1):
  the board outline again, w0.1
Conn. Pos. (M4):
  circle w0.5: c2.361,6 r1.15
  circle w0.5: c17.85,6 r1.15
  circle w0.5: c52.15,6 r1.15
  circle w0.5: c67.65,6 r1.15
  circle w0.5: c67.65,32 r1.15
  circle w0.5: c52.15,32 r1.15
  circle w0.5: c17.85,32.004 r1.15
  circle w0.5: c2.35,32.004 r1.15
  circle w0.35: c31.683,68.008 r0.675
  circle w0.35: c34.223,68.008 r0.675
  circle w0.35: c36.763,68.008 r0.675
  circle w0.35: c39.303,68.008 r0.675
  circle w0.35: c41.843,68.008 r0.675
  circle w0.35: c44.383,68.008 r0.675
  circle w0.25: c16.375,46.443 r0.5
  circle w0.25: c16.375,47.725 r0.5
  circle w0.25: c16.375,48.983 r0.5
  region: 14.91,68.894 12.904,68.894 12.904,66.8 14.91,66.8
  rectangle: 5.429,66.806 7.416,68.894
  rectangle: 11.285,64.32 11.635,66.02
  rectangle: 10.635,64.32 10.985,66.02
  rectangle: 9.985,64.32 10.335,66.02
  rectangle: 9.335,64.32 9.685,66.02
  rectangle: 8.685,64.32 9.035,66.02
  region: 5.68,45.275 5.68,45.625 3.98,45.625 3.98,45.275
  region: 5.68,45.925 5.68,46.275 3.98,46.275 3.98,45.925
  region: 5.68,46.575 5.68,46.925 3.98,46.925 3.98,46.575
  region: 5.68,47.225 5.68,47.575 3.98,47.575 3.98,47.225
  region: 5.68,47.875 5.68,48.225 3.98,48.225 3.98,47.875
  region: 3.193,42.019 3.193,44.006 1.106,44.006 1.106,42.019
  region: 1.106,51.5 1.106,49.494 3.2,49.494 3.2,51.5
  lines w0.1: 1.9,46.75 2.4,46.75 ; 2.15,46.5 2.15,47 ; 9.91,67.85 10.41,67.85 ; 10.16,67.6 10.16,68.1 ; 16.125,47.725 16.625,47.725 ; 16.375,47.475 16.375,47.975 ; 37.531,68.008 38.531,68.008 ; 38.031,67.508 38.031,68.508
  lines w0.125: 9.5,6 10.7,6 ; 9.5,31.999 10.7,31.999 ; 10.1,5.401 10.1,6.601 ; 10.1,31.4 10.1,32.6 ; 59.3,6 60.5,6 ; 59.3,32 60.5,32 ; 59.9,5.399 59.9,6.599 ; 59.9,31.399 59.9,32.599
  lines w0.2: 0.05,0.901 21.4,0.901 21.4,11.001 0.05,11.001 0.05,0.901 ; 0.05,26.9 0.05,37 21.4,37 21.4,26.9 0.05,26.9 ; 48.6,0.999 69.95,0.999 69.95,11.099 48.6,11.099 48.6,0.999 ; 48.6,26.999 69.95,26.999 69.95,37.099 48.6,37.099 48.6,26.999
  text "Connector Placement" at -0.1,77.25 h5
  text "DEBUG CONNECTOR" at 30.7,65.125 h1
  text "DEBUG USB" at 5.85,62.6 h1
  text "I2C" at 15.15,46.35 h1 r90
  text "I2C BRIDGE / USB" at 9.2,41.6 h1 r90
  text "VIN BANANA PLUG" at 2.462,34.75 h1
  text "VOUT BANANA PLUG" at 51.663,34.749 h1
  text "GND BANANA PLUG" at 2.462,8.325 h1
  text "GND BANANA PLUG" at 52.262,8.324 h1
TP Pos. (M5):
  circle w0.4: c42.971,5.223 r1.35
  circle w0.4: c34.843,5.223 r1.35
  circle w0.4: c26.741,5.22 r1.35
  circle w0.4: c64.77,13.605 r1.35
  circle w0.4: c64.77,24.464 r1.35
  circle w0.4: c5.08,13.605 r1.35
  circle w0.4: c5.08,24.464 r1.35
  circle w0.4: c15.494,40.64 r1.35
  circle w0.4: c55.245,40.275 r1.35
  circle w0.4: c62.23,42.815 r1.35
  circle w0.4: c55.245,45.355 r1.35
  circle w0.4: c62.23,47.895 r1.35
  circle w0.4: c55.245,50.435 r1.35
  circle w0.4: c62.23,52.975 r1.35
  circle w0.4: c62.23,58.055 r1.35
  circle w0.4: c55.245,55.515 r1.35
  circle w0.4: c55.245,60.595 r1.35
  circle w0.4: c55.245,65.675 r1.35
  circle w0.4: c49.53,65.675 r1.35
  circle w0.5: c10.795,66.81 r0.25
  circle w0.5: c9.525,66.81 r0.25
  circle w0.5: c9.525,65.54 r0.25
  circle w0.5: c10.795,65.54 r0.25
  circle w0.5: c10.795,64.27 r0.25
  circle w0.5: c9.525,64.27 r0.25
  circle w0.4: c2.54,67.46 r1.35
  circle w0.4: c17.78,67.46 r1.35
  lines w0.1: 4.07,57.82 4.07,66.81 8.52,66.81 ; 5.82,57.82 5.82,65.54 8.52,65.54 ; 7.57,57.82 7.57,64.27 8.52,64.27 ; 8.12,63.87 8.52,64.27 ; 8.12,64.67 8.52,64.27 ; 8.12,65.14 8.52,65.54 ; 8.12,65.94 8.52,65.54 ; 8.12,66.41 8.52,66.81 ; 8.12,67.21 8.52,66.81 ; 12.2,63.87 11.8,64.27 ; 12.2,64.67 11.8,64.27 ; 12.2,66.41 11.8,66.81 ; 12.2,67.21 11.8,66.81 ; 12.75,57.82 12.75,64.27 11.8,64.27 ; 14.5,57.82 14.5,66.81 11.8,66.81
  text "Test Point Placement" at 0.275,77.25 h5
  text "C2INJ" at 47.281,67.65 h1
  text "VOUT" at 53.412,67.65 h1
  text "COMP2" at 52.912,62.57 h1
  text "DCR_CS" at 64.125,58.575 h1
  text "HS_CS" at 52.912,57.49 h1
  text "CT_CS" at 64.125,53.575 h1
  text "PWM_HS" at 52.413,52.41 h1
  text "PWM_LS" at 64.125,48.275 h1
  text "J101-2_GND" at 4.275,48.058 h1 r90
  text "J101-4_VCC" at 6.175,48.058 h1 r90
  text "J101-6_RST" at 8,48.058 h1 r90
  text "J101-5_SWD" at 13.2,48.058 h1 r90
  text "C1INJ" at 53.079,47.33 h1
  text "J101-1_SWCLK" at 14.95,46.225 h1 r90
  text "VOUT" at 64.125,43.3 h1
  text "DEBUG" at 13.161,42.625 h1
  text "COMP1" at 53.079,42.25 h1
  text "2x5 50mil test-point pattern" at -0.625,36.975 h1 r90
  text "VOUT" at 62.937,26.464 h1
  text "VIN" at 3.83,26.4 h1
  text "GND" at 3.747,15.575 h1
  text "GND" at 63.437,15.575 h1
  text "GATE_L" at 23.909,7.19 h1
  text "GATE_H" at 32.011,7.193 h1
  text "SW_NODE" at 39.639,7.193 h1
Dimensions (M6):
  circle w0.4: c8,32 r1.6
  circle w0.4: c8,6 r1.6
  circle w0.4: c62,6 r1.6
  circle w0.4: c62,32 r1.6
  circle w0.4: c62,65 r1.6
  circle w0.4: c17.78,67.46 r1.35
  circle w0.4: c2.54,67.46 r1.35
  text "Mechanical Dimensions" at -0.075,77.275 h5

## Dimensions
42.971,3.873 to 0,0 on TP Pos. (M5)
34.843,3.873 to 0,0 on TP Pos. (M5)
26.741,3.87 to 0,0 on TP Pos. (M5)
70,0 to 44.321,5.223 on TP Pos. (M5)
70,0 to 66.12,24.464 on TP Pos. (M5)
70,0 to 66.12,13.605 on TP Pos. (M5)
56.595,40.275 to 70,70 on TP Pos. (M5)
63.58,42.815 to 70,70 on TP Pos. (M5)
56.595,45.355 to 70,70 on TP Pos. (M5)
63.67,47.72 to 70,70 on TP Pos. (M5)
56.595,50.435 to 70,70 on TP Pos. (M5)
63.58,52.975 to 70,70 on TP Pos. (M5)
56.595,55.515 to 70,70 on TP Pos. (M5)
63.58,58.055 to 70,70 on TP Pos. (M5)
56.595,60.595 to 70,70 on TP Pos. (M5)
56.595,65.675 to 70,70 on TP Pos. (M5)
62.23,41.465 to 0,0 on TP Pos. (M5)
55.245,38.925 to 0,0 on TP Pos. (M5)
49.53,64.325 to 0,0 on TP Pos. (M5)
15.494,39.29 to 0,0 on TP Pos. (M5)
64.77,12.255 to 0,0 on TP Pos. (M5)
5.08,12.255 to 0,0 on TP Pos. (M5)
0,0 to 3.73,24.464 on TP Pos. (M5)
0,0 to 3.73,13.605 on TP Pos. (M5)
1.19,67.46 to 0,70 on TP Pos. (M5)
2.54,68.81 to 0,70 on TP Pos. (M5)
70,70 to 38.531,68.008 on Conn. Pos. (M4)
38.031,68.508 to 70,70 on Conn. Pos. (M4)
70,70 to 16.35,47.734 on Conn. Pos. (M4)
0,70 to 2.15,47 on Conn. Pos. (M4)
0,70 to 10.16,68.1 on Conn. Pos. (M4)
0,70 to 9.91,67.85 on Conn. Pos. (M4)
16.125,47.725 to 0,70 on Conn. Pos. (M4)
1.9,46.75 to 0,70 on Conn. Pos. (M4)
62,6 to 70.453,14.453 on Dimensions (M6)
62,32 to 70.529,23.771 on Dimensions (M6)
62,65 to 54.715,72.285 on Dimensions (M6)
17.78,67.46 to 22.568,72.248 on Dimensions (M6)
0,0 to 62,30.4 on Dimensions (M6)
0,0 to 8,30.4 on Dimensions (M6)
60.4,6 to 0,0 on Dimensions (M6)
60.4,32 to 0,0 on Dimensions (M6)
9.525,64.02 to 10.795,64.02 on TP Pos. (M5)
9.275,66.81 to 1.19,67.46 on TP Pos. (M5)
9.525,67.06 to 2.54,68.81 on TP Pos. (M5)
10.795,67.06 to 2.54,68.81 on TP Pos. (M5)
0,0 to 59.9,5.399 on Conn. Pos. (M4)
63.6,65 to 70,70 on Dimensions (M6)
70,70 to 62,66.6 on Dimensions (M6)
2.54,68.81 to 0,70 on Dimensions (M6)
0,0 to 10.1,5.401 on Conn. Pos. (M4)
9.5,6 to 0,0 on Conn. Pos. (M4)
9.5,31.999 to 0,0 on Conn. Pos. (M4)
1.19,67.46 to 0,0 on Dimensions (M6)
17.78,68.81 to 2.54,68.81 on Dimensions (M6)
0,70 to 0,0 on Dimensions (M6)
0,0 to 70,0 on Dimensions (M6)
